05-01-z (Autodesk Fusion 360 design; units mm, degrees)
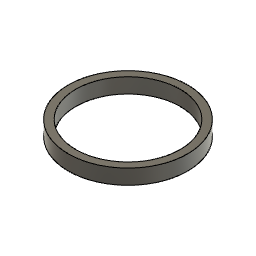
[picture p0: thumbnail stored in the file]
sketch "スケッチ" plane through (0, 0, 0) normal (0, 0, 1) x axis (1, 0, 0)
  line L1 (-7, -2) -> (-8, -2)
  line L2 (-7, 0) -> (-7, -2)
  line L3 (-8, 0) -> (-7, 0)
  line L4 (-8, -2) -> (-8, 0)
  line L5 (0, 22.5) -> (0, 1.75)
  point P1 (0, 0)
  point P4 (-7, 0)
  point P2 (-8, -2)
  point P3 (-7, -2)
  point P5 (-8, 0)
  horizontal L1
  vertical L2
  horizontal L3
  vertical L4
  horizontal P1 P4
  dimension "d1" distance P2 P3 = 1
  dimension "d2" distance P2 P5 = 2
  dimension "d3" = 16
revolve "回転" sketch "スケッチ" AlongAngle 360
